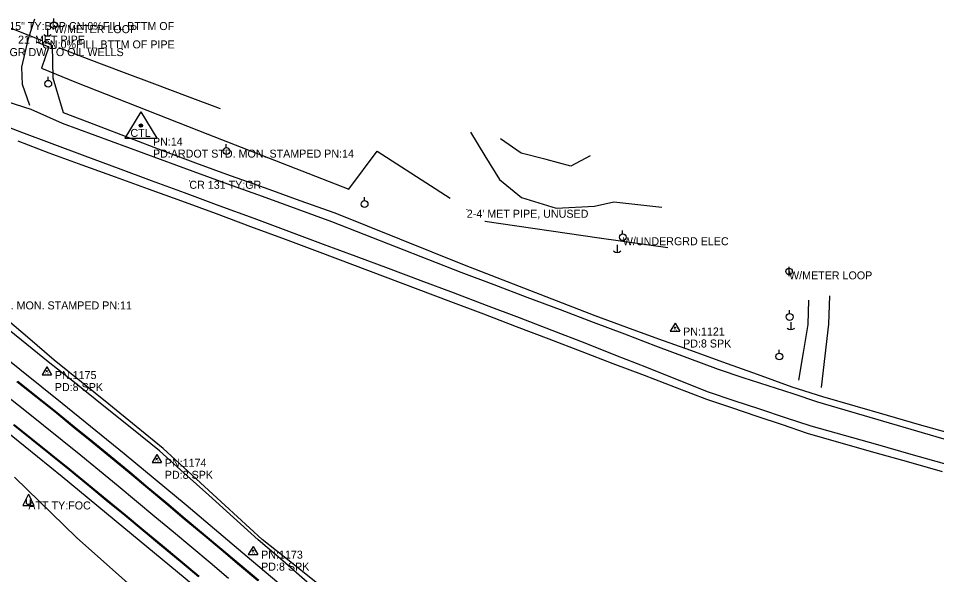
# Model space of a CAD drawing. Extents: x 878399 to 889864, y 1564003 to 1567413.
# Drawn here: x 883520 to 884094, y 1566437 to 1566785 of the extents above; entities that cross this region are included whole.
import ezdxf

# ---------------------------------------------------------------- set-up
doc = ezdxf.new("R2010")
doc.units = 0
for name, color, linetype in [('S_DITCHLINE', 7, 'Continuous'), ('S_DRG_PT_SYM', 7, 'Continuous'), ('S_DRIVEWAY', 7, 'Continuous'), ('S_EDGE_PAVEMENT', 7, 'Continuous'), ('S_FENCE', 7, 'Continuous'), ('S_FIBER_OPTIC_CABLE', 7, 'Continuous'), ('S_GATE_ANNOT', 7, 'Continuous'), ('S_GRAVEL_ROAD', 7, 'Continuous'), ('S_MSC_PT_SYM', 7, 'Continuous'), ('S_PAVEMENT_CROWN', 7, 'Continuous'), ('S_PRIMARY_CTL', 7, 'Continuous'), ('S_PRIMARY_CTL_ANNOT', 7, 'Continuous'), ('S_SECONDARY_CTL', 7, 'Continuous'), ('S_SECONDARY_CTL_ANNOT', 7, 'Continuous'), ('S_SHOULDER', 7, 'Continuous'), ('S_SIDE_DRAIN', 7, 'Continuous'), ('S_SIDE_DRAIN_ANNOT', 7, 'Continuous'), ('S_SURVEY_TEXT_ANNOT', 7, 'Continuous'), ('S_UTILITY_POLE', 7, 'Continuous'), ('S_UTILITY_POLE_ANNOT', 7, 'Continuous'), ('S_UTL_PT_SYM', 7, 'Continuous')]:
    doc.layers.add(name, color=color, linetype=linetype)

msp = doc.modelspace()

# ---------------------------------------------------------------- linework, layer by layer
at = {"layer": 'S_DITCHLINE'}
for points in [[(883536.75, 1566770.69), (883541.48, 1566767.91), (883541.92, 1566747.74), (883548.44, 1566726), (883569.09, 1566718.13), (883589.73, 1566710.27), (883610.38, 1566702.41), (883631.02, 1566694.54), (883652.77, 1566686.74), (883674.52, 1566678.94), (883696.26, 1566671.14), (883718.01, 1566663.34), (883738.22, 1566655.23), (883758.43, 1566647.12), (883778.65, 1566639.01), (883798.86, 1566630.9), (883819.26, 1566622.95), (883839.67, 1566615.01), (883860.07, 1566607.06), (883880.48, 1566599.11), (883900.41, 1566591.88), (883920.34, 1566584.65), (883940.28, 1566577.42), (883960.21, 1566570.19), (883981.88, 1566562.43), (884003.56, 1566554.66), (884022.79, 1566548.49), (884042.93, 1566542.69), (884063.08, 1566536.89), (884083.22, 1566531.09), (884103.37, 1566525.29)], [(883546.05, 1566766.6), (883564.36, 1566759.33), (883584.86, 1566751.64), (883605.36, 1566743.95), (883625.86, 1566736.27), (883646.36, 1566728.58)], [(883520.06, 1566708.29), (883539.35, 1566700.82), (883560.08, 1566693.35), (883580.81, 1566685.88), (883601.55, 1566678.42), (883622.28, 1566670.95), (883643.87, 1566662.9), (883665.46, 1566654.85), (883687.05, 1566646.8), (883708.64, 1566638.75), (883729.07, 1566631.05), (883749.51, 1566623.35), (883769.95, 1566615.65), (883790.38, 1566607.95), (883810.86, 1566600.12), (883831.34, 1566592.3), (883851.82, 1566584.48), (883872.3, 1566576.65), (883891.78, 1566569.21), (883911.26, 1566561.77), (883930.74, 1566554.33), (883950.21, 1566546.88), (883965.97, 1566541.56), (883981.72, 1566536.24), (883997.47, 1566530.92), (884013.22, 1566525.6), (884034.31, 1566519.61), (884055.39, 1566513.61), (884076.48, 1566507.61), (884097.56, 1566501.62)], [(883700.87, 1566432.48), (883685.5, 1566445.7), (883670.13, 1566458.93), (883654.76, 1566472.83), (883639.38, 1566486.73), (883624, 1566500.62), (883608.63, 1566514.52), (883591.21, 1566528.46), (883573.79, 1566542.4), (883556.37, 1566556.34), (883538.95, 1566570.28), (883522.27, 1566583.65), (883505.58, 1566597.03)], [(883868.52, 1566293.82), (883852.98, 1566309.2), (883838.44, 1566321.88), (883823.9, 1566334.56), (883809.35, 1566347.24), (883794.81, 1566359.92), (883782.15, 1566370.5), (883769.5, 1566381.09), (883756.84, 1566391.67), (883744.19, 1566402.26), (883726.29, 1566416.45), (883708.4, 1566430.65), (883690.51, 1566444.84), (883672.62, 1566459.03), (883657.19, 1566473.28), (883641.76, 1566487.53), (883626.33, 1566501.78), (883610.9, 1566516.03), (883593.87, 1566529.85), (883576.85, 1566543.67), (883559.83, 1566557.49), (883542.8, 1566571.31), (883526.07, 1566585.55), (883509.35, 1566599.78)]]:
    msp.add_lwpolyline(points, dxfattribs=at)
at = {"layer": 'S_DRG_PT_SYM'}
msp.add_lwpolyline([(883535.2, 1566771.15), (883535.2, 1566771.2), (883535.2, 1566771.15), (883535.15, 1566771.15), (883535.2, 1566771.15), (883535.2, 1566771.1), (883535.2, 1566771.15), (883535.25, 1566771.15)], dxfattribs=at)
at = {"layer": 'S_DRIVEWAY'}
for points in [[(883527.51, 1566730.5), (883522.97, 1566743.57), (883522.61, 1566754.35), (883526.72, 1566772.29), (883530.7, 1566784.55)], [(884014.05, 1566608.69), (884013.6, 1566593.58), (884010.7, 1566576.11), (884007.8, 1566558.64)], [(884022.09, 1566554.13), (884024.38, 1566573.98), (884026.68, 1566593.83), (884027.36, 1566611.4)]]:
    msp.add_lwpolyline(points, dxfattribs=at)
at = {"layer": 'S_EDGE_PAVEMENT'}
for points in [[(883519.45, 1566557.95), (883531.16, 1566548.58), (883543.03, 1566539.09), (883554.67, 1566529.62), (883566.3, 1566520.15), (883577.94, 1566510.69), (883589.48, 1566501.1), (883589.48, 1566501.1), (883589.48, 1566501.1), (883600.97, 1566491.45), (883612.54, 1566481.73), (883612.54, 1566481.73), (883624.03, 1566472.08), (883624.03, 1566472.08), (883635.52, 1566462.44), (883635.52, 1566462.44), (883635.52, 1566462.44), (883647.01, 1566452.8), (883647.01, 1566452.8), (883647.01, 1566452.8), (883658.5, 1566443.15), (883670.03, 1566433.45)], [(883519.93, 1566558.17), (883531.64, 1566548.8), (883543.51, 1566539.31), (883555.15, 1566529.85), (883566.78, 1566520.38), (883578.42, 1566510.91), (883589.96, 1566501.33), (883589.96, 1566501.33), (883589.96, 1566501.33), (883601.44, 1566491.68), (883613.02, 1566481.96), (883613.02, 1566481.96), (883624.51, 1566472.31), (883624.51, 1566472.31), (883636, 1566462.67), (883636, 1566462.67), (883636, 1566462.67), (883647.49, 1566453.03), (883647.49, 1566453.03), (883647.49, 1566453.03), (883658.98, 1566443.38), (883670.5, 1566433.68)], [(883517.25, 1566530.85), (883528.73, 1566521.62), (883540.43, 1566512.22), (883540.43, 1566512.22), (883552.12, 1566502.82), (883563.71, 1566493.3), (883575.29, 1566483.77), (883586.88, 1566474.24), (883598.32, 1566464.79), (883609.87, 1566455.21), (883621.41, 1566445.63), (883632.92, 1566436.01)], [(883517.73, 1566531.08), (883529.21, 1566521.85), (883540.91, 1566512.45), (883540.91, 1566512.45), (883552.6, 1566503.05), (883564.18, 1566493.53), (883575.77, 1566484), (883587.36, 1566474.48), (883598.79, 1566465.02), (883610.34, 1566455.44), (883621.89, 1566445.86), (883633.4, 1566436.24)]]:
    msp.add_lwpolyline(points, dxfattribs=at)
at = {"layer": 'S_FENCE'}
for p, q in [((883531.65, 1566770.27), (883539.35, 1566767.04)), ((883539.35, 1566767.04), (883534.8, 1566753.81)), ((883534.8, 1566753.81), (883556.65, 1566744.79)), ((883556.65, 1566744.79), (883638.7, 1566712.61)), ((883638.7, 1566712.61), (883726.8, 1566678.11)), ((883726.8, 1566678.11), (883744.56, 1566701.89)), ((883744.56, 1566701.89), (883790.17, 1566672.48)), ((883811.9, 1566658.13), (883883.29, 1566647.77)), ((883883.29, 1566647.77), (883926.09, 1566641.63))]:
    msp.add_line(p, q, dxfattribs=at)
at = {"layer": 'S_FIBER_OPTIC_CABLE'}
for p, q in [((883556.64, 1566460.44), (883517.92, 1566498)), ((883596.33, 1566425.08), (883556.64, 1566460.44))]:
    msp.add_line(p, q, dxfattribs=at)
at = {"layer": 'S_GRAVEL_ROAD'}
for points in [[(883513.09, 1566732.98), (883528.15, 1566728.08), (883547.69, 1566719.34), (883568.08, 1566711.85), (883588.48, 1566704.37), (883608.87, 1566696.88), (883629.27, 1566689.4), (883650.97, 1566681.55), (883672.67, 1566673.71), (883694.37, 1566665.86), (883716.08, 1566658.02), (883736.24, 1566650.08), (883756.41, 1566642.13), (883776.58, 1566634.19), (883796.74, 1566626.25), (883817.44, 1566618.45), (883838.13, 1566610.65), (883858.82, 1566602.85), (883879.51, 1566595.05), (883899, 1566587.66), (883918.5, 1566580.28), (883937.99, 1566572.9), (883957.48, 1566565.51), (883973.04, 1566560.45), (883988.59, 1566555.38), (884004.14, 1566550.31), (884019.7, 1566545.25), (884040.32, 1566539.2), (884060.95, 1566533.16), (884081.57, 1566527.11), (884102.2, 1566521.06)], [(883503.2, 1566720.99), (883522.24, 1566713.85), (883541.28, 1566706.71), (883561.96, 1566699.03), (883582.64, 1566691.34), (883603.31, 1566683.66), (883623.99, 1566675.97), (883645.69, 1566667.94), (883667.38, 1566659.92), (883689.08, 1566651.89), (883710.77, 1566643.86), (883731.1, 1566636.28), (883751.42, 1566628.7), (883771.74, 1566621.12), (883792.07, 1566613.54), (883812.61, 1566605.68), (883833.16, 1566597.81), (883853.7, 1566589.95), (883874.24, 1566582.09), (883893.51, 1566574.42), (883912.78, 1566566.76), (883932.05, 1566559.09), (883951.32, 1566551.42), (883967.33, 1566546.11), (883983.35, 1566540.79), (883999.37, 1566535.48), (884015.39, 1566530.17), (884036.25, 1566524.29), (884057.11, 1566518.42), (884077.97, 1566512.55), (884098.83, 1566506.67)], [(883802.75, 1566713.76), (883811.9, 1566698.99), (883821.05, 1566684.23), (883834.68, 1566672.9), (883856.3, 1566666.25), (883880.4, 1566667.59), (883892.34, 1566670.26), (883907.39, 1566668.54), (883922.44, 1566666.83)], [(883877.68, 1566698.99), (883865.56, 1566692.5), (883850.07, 1566696.62), (883834.58, 1566700.73), (883821.51, 1566709.69)]]:
    msp.add_lwpolyline(points, dxfattribs=at)
at = {"layer": 'S_MSC_PT_SYM'}
for points in [[(883531.65, 1566770.27), (883531.65, 1566770.32), (883531.65, 1566770.27), (883531.6, 1566770.27), (883531.65, 1566770.27), (883531.65, 1566770.22), (883531.65, 1566770.27), (883531.7, 1566770.27)], [(883539.35, 1566767.04), (883539.35, 1566767.09), (883539.35, 1566767.04), (883539.3, 1566767.04), (883539.35, 1566767.04), (883539.35, 1566766.99), (883539.35, 1566767.04), (883539.4, 1566767.04)], [(883534.8, 1566753.81), (883534.8, 1566753.86), (883534.8, 1566753.81), (883534.75, 1566753.81), (883534.8, 1566753.81), (883534.8, 1566753.76), (883534.8, 1566753.81), (883534.85, 1566753.81)], [(883556.65, 1566744.79), (883556.65, 1566744.84), (883556.65, 1566744.79), (883556.6, 1566744.79), (883556.65, 1566744.79), (883556.65, 1566744.74), (883556.65, 1566744.79), (883556.7, 1566744.79)], [(883638.7, 1566712.61), (883638.7, 1566712.66), (883638.7, 1566712.61), (883638.65, 1566712.61), (883638.7, 1566712.61), (883638.7, 1566712.56), (883638.7, 1566712.61), (883638.75, 1566712.61)], [(883744.56, 1566701.89), (883744.56, 1566701.94), (883744.56, 1566701.89), (883744.51, 1566701.89), (883744.56, 1566701.89), (883744.56, 1566701.84), (883744.56, 1566701.89), (883744.61, 1566701.89)], [(883627.19, 1566683.38), (883627.19, 1566683.43), (883627.19, 1566683.38), (883627.14, 1566683.38), (883627.19, 1566683.38), (883627.19, 1566683.33), (883627.19, 1566683.38), (883627.24, 1566683.38)], [(883726.8, 1566678.11), (883726.8, 1566678.16), (883726.8, 1566678.11), (883726.75, 1566678.11), (883726.8, 1566678.11), (883726.8, 1566678.06), (883726.8, 1566678.11), (883726.85, 1566678.11)], [(883790.17, 1566672.48), (883790.17, 1566672.53), (883790.17, 1566672.48), (883790.12, 1566672.48), (883790.17, 1566672.48), (883790.17, 1566672.43), (883790.17, 1566672.48), (883790.22, 1566672.48)], [(883800.55, 1566665.28), (883800.55, 1566665.33), (883800.55, 1566665.28), (883800.5, 1566665.28), (883800.55, 1566665.28), (883800.55, 1566665.23), (883800.55, 1566665.28), (883800.6, 1566665.28)], [(883811.9, 1566658.13), (883811.9, 1566658.18), (883811.9, 1566658.13), (883811.85, 1566658.13), (883811.9, 1566658.13), (883811.9, 1566658.08), (883811.9, 1566658.13), (883811.95, 1566658.13)], [(883883.29, 1566647.77), (883883.29, 1566647.82), (883883.29, 1566647.77), (883883.24, 1566647.77), (883883.29, 1566647.77), (883883.29, 1566647.72), (883883.29, 1566647.77), (883883.34, 1566647.77)], [(883926.09, 1566641.63), (883926.09, 1566641.68), (883926.09, 1566641.63), (883926.04, 1566641.63), (883926.09, 1566641.63), (883926.09, 1566641.58), (883926.09, 1566641.63), (883926.14, 1566641.63)]]:
    msp.add_lwpolyline(points, dxfattribs=at)
at = {"layer": 'S_PAVEMENT_CROWN'}
msp.add_lwpolyline([(883512.62, 1566549.25), (883524.38, 1566539.94), (883536.11, 1566530.63), (883547.8, 1566521.23), (883559.41, 1566511.74), (883571.03, 1566502.25), (883582.63, 1566492.73), (883582.63, 1566492.73), (883594.16, 1566483.14), (883605.68, 1566473.55), (883617.2, 1566463.95), (883628.7, 1566454.31), (883640.18, 1566444.66), (883640.18, 1566444.66), (883651.67, 1566435.01)], dxfattribs=at)
at = {"layer": 'S_PRIMARY_CTL'}
for p, q in [((883596.95, 1566726.57), (883586.91, 1566710.06)), ((883596.95, 1566726.57), (883606.77, 1566710.06)), ((883586.91, 1566710.06), (883606.77, 1566710.06))]:
    msp.add_line(p, q, dxfattribs=at)
for radius in [1.04, 0.609, 0.344]:
    msp.add_circle((883596.95, 1566717.87), radius, dxfattribs=at)
at = {"layer": 'S_SECONDARY_CTL'}
for p, q in [((883930.67, 1566594.27), (883927.66, 1566589.31)), ((883930.67, 1566594.27), (883933.62, 1566589.31)), ((883927.66, 1566589.31), (883933.62, 1566589.31)), ((883538.13, 1566567.03), (883535.12, 1566562.07)), ((883535.12, 1566562.07), (883541.08, 1566562.07)), ((883538.13, 1566567.03), (883541.08, 1566562.07)), ((883606.86, 1566512.17), (883603.85, 1566507.21)), ((883606.86, 1566512.17), (883609.81, 1566507.21)), ((883603.85, 1566507.21), (883609.81, 1566507.21)), ((883667.04, 1566454.76), (883664.03, 1566449.8)), ((883667.04, 1566454.76), (883669.98, 1566449.8)), ((883664.03, 1566449.8), (883669.98, 1566449.8))]:
    msp.add_line(p, q, dxfattribs=at)
for centre, radius in [((883930.67, 1566591.65), 0.311), ((883930.67, 1566591.65), 0.183), ((883930.67, 1566591.65), 0.103), ((883538.13, 1566564.42), 0.311), ((883538.13, 1566564.42), 0.183), ((883538.13, 1566564.42), 0.103), ((883606.86, 1566509.56), 0.311), ((883606.86, 1566509.56), 0.183), ((883606.86, 1566509.56), 0.103), ((883667.04, 1566452.15), 0.311), ((883667.04, 1566452.15), 0.183), ((883667.04, 1566452.15), 0.103)]:
    msp.add_circle(centre, radius, dxfattribs=at)
at = {"layer": 'S_SHOULDER'}
for points in [[(883508.31, 1566575.84), (883547.66, 1566544.44), (883586.44, 1566512.88), (883625.11, 1566480.84), (883663.31, 1566448.58), (883701.62, 1566416.27), (883739.86, 1566383.96), (883777.89, 1566351.48), (883815.94, 1566319.17), (883853.96, 1566286.62), (883891.95, 1566254.11), (883929.94, 1566221.59), (883967.85, 1566188.94), (884005.75, 1566156.31), (884043.67, 1566123.7), (884081.66, 1566091.2), (884119.53, 1566058.67), (884157.51, 1566026.01), (884195.58, 1565993.6), (884233.66, 1565961.2), (884271.59, 1565928.53), (884288.54, 1565909.45), (884315.55, 1565882.9), (884321.54, 1565877.6)], [(883509.1, 1566529.69), (883547.7, 1566498.51), (883586.27, 1566466.69), (883624.58, 1566434.92), (883662.64, 1566402.69), (883700.84, 1566370.42), (883738.86, 1566338.05), (883776.89, 1566305.59), (883814.92, 1566272.98), (883852.88, 1566240.51), (883890.94, 1566208.08), (883928.89, 1566175.58), (883966.88, 1566143.07), (884004.67, 1566110.33), (884042.61, 1566077.76), (884080.7, 1566045.23), (884118.58, 1566012.73), (884156.35, 1565979.97), (884194.27, 1565947.36), (884231.98, 1565914.52), (884270.03, 1565882.19), (884310.06, 1565851.92)]]:
    msp.add_lwpolyline(points, dxfattribs=at)
at = {"layer": 'S_SIDE_DRAIN'}
msp.add_line((883506.09, 1566782.62), (883535.2, 1566771.15), dxfattribs=at)
at = {"layer": 'S_UTILITY_POLE'}
for p, q in [((883542.44, 1566782.83), (883542.44, 1566784.94)), ((883538.45, 1566778.67), (883538.45, 1566773.94)), ((883538.88, 1566746.18), (883538.88, 1566748.29)), ((883650.27, 1566704.12), (883650.27, 1566706.23)), ((883736.53, 1566670.99), (883736.53, 1566673.1)), ((883897.9, 1566650.23), (883897.9, 1566652.33)), ((883894.39, 1566643.29), (883894.39, 1566638.56)), ((884001.87, 1566623.82), (884001.87, 1566629.61)), ((884002.1, 1566600.37), (884002.1, 1566602.48)), ((884003, 1566595.07), (884003, 1566590.35)), ((883995.72, 1566575.65), (883995.72, 1566577.75)), ((883526.6, 1566487.45), (883523.08, 1566480.36)), ((883526.6, 1566487.45), (883530.09, 1566480.36)), ((883525.4, 1566481.6), (883525.4, 1566484.04)), ((883526.02, 1566480.94), (883525.4, 1566481.6)), ((883527.77, 1566481.6), (883527.22, 1566480.94)), ((883527.77, 1566484.04), (883527.77, 1566481.6)), ((883523.08, 1566480.36), (883530.09, 1566480.36)), ((883527.22, 1566480.94), (883526.02, 1566480.94))]:
    msp.add_line(p, q, dxfattribs=at)
for centre, radius in [((883542.56, 1566780.69), 2.13), ((883539, 1566744.04), 2.13), ((883650.39, 1566701.98), 2.13), ((883736.65, 1566668.85), 2.13), ((883898.02, 1566648.08), 2.13), ((884001.87, 1566626.75), 2.05), ((884002.22, 1566598.23), 2.13), ((883995.84, 1566573.51), 2.13)]:
    msp.add_circle(centre, radius, dxfattribs=at)
for centre in [(883538.51, 1566777.37), (883894.45, 1566641.99), (884003.07, 1566593.77)]:
    msp.add_arc(centre, 3.41, 226.39718, 313.60282, dxfattribs=at)
at = {"layer": 'S_UTL_PT_SYM'}
msp.add_lwpolyline([(883556.64, 1566460.44), (883556.64, 1566460.49), (883556.64, 1566460.44), (883556.59, 1566460.44), (883556.64, 1566460.44), (883556.64, 1566460.39), (883556.64, 1566460.44), (883556.69, 1566460.44)], dxfattribs=at)

# ---------------------------------------------------------------- texts
at = {"layer": 'S_GATE_ANNOT'}
for s, p in [("21' MET PIPE", (883520.16, 1566769.14)), ("2-4' MET PIPE, UNUSED", (883800.55, 1566660.28))]:
    msp.add_text(s, height=5, dxfattribs=at).set_placement(p)
at = {"layer": 'S_PRIMARY_CTL'}
msp.add_text('CTL', height=5, rotation=360, dxfattribs=at).set_placement((883590.36, 1566710.8))
at = {"layer": 'S_PRIMARY_CTL_ANNOT'}
for s, p in [('PN:14', (883604.45, 1566705.37)), ('PD:ARDOT STD. MON. STAMPED PN:14', (883604.45, 1566697.87)), ('PD:ARDOT STD. MON. STAMPED PN:11', (883465.76, 1566602.97))]:
    msp.add_text(s, height=5, dxfattribs=at).set_placement(p)
at = {"layer": 'S_SECONDARY_CTL'}
for p in [(883929.47, 1566589.64), (883536.93, 1566562.41), (883605.66, 1566507.54), (883665.83, 1566450.13)]:
    msp.add_text('TV', height=1.5, rotation=360, dxfattribs=at).set_placement(p)
at = {"layer": 'S_SECONDARY_CTL_ANNOT'}
for s, p in [('PN:1121', (883935.67, 1566586.65)), ('PD:8 SPK', (883935.67, 1566579.15)), ('PN:1175', (883543.13, 1566559.42)), ('PD:8 SPK', (883543.13, 1566551.92)), ('PN:1174', (883611.86, 1566504.56)), ('PD:8 SPK', (883611.86, 1566497.06)), ('PN:1173', (883672.04, 1566447.15)), ('PD:8 SPK', (883672.04, 1566439.65))]:
    msp.add_text(s, height=5, dxfattribs=at).set_placement(p)
at = {"layer": 'S_SIDE_DRAIN_ANNOT'}
for s, p in [('DI:15" TY:BPP CN:0%FILL BTTM OF', (883506.09, 1566777.62)), ('CN:0%FILL BTTM OF PIPE', (883535.2, 1566766.15))]:
    msp.add_text(s, height=5, dxfattribs=at).set_placement(p)
at = {"layer": 'S_SURVEY_TEXT_ANNOT'}
for s, p in [('GR DW TO OIL WELLS', (883514.83, 1566761.34)), ('CR 131 TY:GR', (883627.19, 1566678.38))]:
    msp.add_text(s, height=5, dxfattribs=at).set_placement(p)
at = {"layer": 'S_UTILITY_POLE_ANNOT'}
for s, p in [('W/METER LOOP', (883542.56, 1566775.69)), ('W/UNDERGRD ELEC', (883898.02, 1566643.08)), ('W/METER LOOP', (884001.87, 1566621.75)), ('ATT TY:FOC', (883526.6, 1566477.91))]:
    msp.add_text(s, height=5, dxfattribs=at).set_placement(p)

doc.saveas('drawing.dxf')
